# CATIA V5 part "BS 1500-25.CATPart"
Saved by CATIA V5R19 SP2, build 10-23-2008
Part number: BS 1500-25
Bounding box of the stored display mesh (mm): x -31.459 to 31.459, y -31.459 to 31.459, z 0 to 94
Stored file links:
  C:\Users\Bora\Desktop\3D Katı model\BS serisi\BS 1500\BS 1500-25.CATPart
  C:\Program Files\Dassault Systemes\B19\intel_a\reffiles\standard\MetricThickPitch.txt
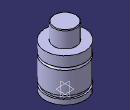
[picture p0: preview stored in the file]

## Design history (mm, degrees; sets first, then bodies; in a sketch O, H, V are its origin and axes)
Body1 (main body)
  Sketch1 on yz-plane, origin (0, 0, 0), H (0, 1, 0), V (0, 0, 1)
    point P1 (31.5, 52)
    point P2 (31.5, 48)
    point P3 (31.5, 52)
    point P7 (18, 93)
    point P9 (18, 93)
    point P14 (31.5, 48)
    arc A1 centre (31.5, 50) radius 2 from (31.5, 52) to (31.5, 48) ccw
    line L1 (31.5, 52) -> (31.5, 68)
    line L2 (31.5, 0) -> (31.5, 8)
    arc A2 centre (17, 93) radius 1 from (18, 93) to (17, 94) ccw
    line L3 (18, 93) -> (18, 68)
    line L4 (29, 13) -> (29, 8)
    line L5 (31.5, 13) -> (31.5, 48)
    line L6 (17, 94) -> (0, 94)
    point P15 (0, 94)
    line L7 (18, 68) -> (31.5, 68)
    line L8 (0, 0) -> (31.5, 0)
    line L9 (29, 13) -> (31.5, 13)
    line L10 (29, 8) -> (31.5, 8)
    coincidence: P15 V, P1 P3, P2 P14, P7 P9
    tangency: L6 A2
    horizontal: L7 H, L8 H, L9 H, L10 H
  Shaft1: profile Sketch1, axis Sketch1.V, angle 360
  Sketch2 on face of Shaft1 from Sketch1.L8, origin (0, 0, 0), H (1, 0, 0), V (0, -1, 0)
    point P1 (10, 0)
    distance P1 V = 10
  Hole1: placed by Sketch2, at (10, 0, 0) direction (0, 0, 1), diameter 6.647, depth 5, threaded "M8", thread diameter 8, thread depth 5, pitch 1.25
  CircPattern1: of Hole1, instances 2, angular step 180, axis from xy-plane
